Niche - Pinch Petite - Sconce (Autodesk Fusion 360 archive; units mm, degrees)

design "Elongated Sconce - Pinch Petite" references "Elongated Sconce - Helio", "Pinch Petite"
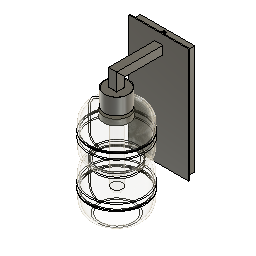
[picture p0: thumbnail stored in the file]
external_derived "ExternalDerived1" bodies "Back Plate", "Knurled Shade Ring", "Screw Top", "Socket Cover", "Screw Bottom", "Socket - E26", "Sconce", "T9-Bulb"
derived_instance "DerivedInstance1"
derived_instance "DerivedInstance2"
derived_instance "DerivedInstance3"
derived_instance "DerivedInstance4"
derived_instance "DerivedInstance5"
derived_instance "DerivedInstance6"
derived_instance "DerivedInstance7"
derived_instance "DerivedInstance8"
derived_instance "DerivedInstance9"
external_derived "ExternalDerived2" bodies "Body1"
align "Align1"
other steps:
derived_base_feature "Derived Base Feature1" bodies "Back Plate"
derived_base_feature "Derived Base Feature1" bodies "Knurled Shade Ring"
derived_base_feature "Derived Base Feature1" bodies "Screw Top"
derived_base_feature "Derived Base Feature1" bodies "Socket Cover"
derived_base_feature "Derived Base Feature1" bodies "Screw Bottom"
derived_base_feature "Derived Base Feature1" bodies "Socket - E26"
derived_base_feature "Derived Base Feature1" bodies "Sconce"
derived_base_feature "Derived Base Feature1" bodies "T9-Bulb"
derived_base_feature "Derived Base Feature1" bodies "E26 Base"
derived_base_feature "Derived Base Feature2" bodies "Body1"
derived_base_feature "Derived Base Feature" bodies "Back Plate", "Screw Top", "Knurled Shade Ring", "Body34"
create_component "CreateComponent1"
create_component "CreateComponent2"
create_component "CreateComponent3"
create_component "CreateComponent4"
create_component "CreateComponent5"
create_component "CreateComponent6"
create_component "CreateComponent7"
create_component "CreateComponent8"
create_component "CreateComponent9"
named bodies: "Back Plate", "Screw Top", "Knurled Shade Ring", "Body1", "Body34", "Sconce", "Socket Cover", "Screw Bottom", "Socket - E26", "T9-Bulb", "E26 Base"

design "Elongated Sconce - Helio"
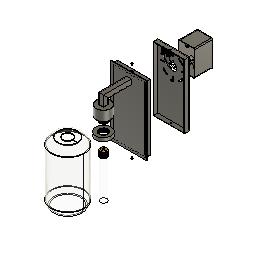
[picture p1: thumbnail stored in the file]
derived_base_feature "Derived Base Feature1" bodies "T9-Bulb", "Helio"
derived_base_feature "Derived Base Feature2" bodies "Back Plate", "Socket Cover", "Screw Top", "Screw Bottom", "Knurled Shade Ring", "Socket - E26"
derived_base_feature "Derived Base Feature3" bodies "E26 Base"
move "Move1"
component_from_bodies "Body->Comp1"
component_from_bodies "Body->Comp2"
component_from_bodies "Body->Comp3"
component_from_bodies "Body->Comp4"
component_from_bodies "Body->Comp5"
component_from_bodies "Body->Comp6"
component_from_bodies "Body->Comp7"
component_from_bodies "Body->Comp8"
component_from_bodies "Body->Comp9"
component_from_bodies "Body->Comp10"
derived_base_feature "Derived Base Feature5" bodies "screw1", "screw1 (1)", "Body1"
move "Move3"
move "Move4"
move "Move5"
move "Move6"
component_from_bodies "Body->Comp11"
component_from_bodies "Body->Comp12"
component_from_bodies "Body->Comp13"
component_from_bodies "Body->Comp14"
component_from_bodies "Body->Comp15"
component_from_bodies "Body->Comp16"
component_from_bodies "Body->Comp17"
component_from_bodies "Body->Comp18"
component_from_bodies "Body->Comp19"
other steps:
base_feature "Base Feature1" bodies "T9-Bulb"
base_feature "Base Feature1" bodies "E26 Base"
base_feature "Base Feature1" bodies "Body1"
base_feature "Base Feature1" bodies "Body1 (1) (1)"
base_feature "Base Feature1" bodies "Body9"
base_feature "Base Feature1" bodies "Body7"
base_feature "Base Feature1" bodies "Body6"
base_feature "Base Feature1" bodies "screw1"
base_feature "Base Feature1" bodies "Body4"
base_feature "Base Feature1" bodies "screw1 (1)"
base_feature "Base Feature1" bodies "Body1 (1)"
base_feature "Base Feature1" bodies "Helio"
base_feature "Base Feature1" bodies "Back Plate"
base_feature "Base Feature1" bodies "Knurled Shade Ring"
base_feature "Base Feature1" bodies "Screw Top"
base_feature "Base Feature1" bodies "Sconce"
base_feature "Base Feature1" bodies "Socket Cover"
base_feature "Base Feature1" bodies "Screw Bottom"
base_feature "Base Feature1" bodies "Socket - E26"
create_component "CreateComponent1"
remove_body "RemoveBody1"
create_component "CreateComponent2"
remove_body "RemoveBody2"
create_component "CreateComponent3"
remove_body "RemoveBody3"
create_component "CreateComponent4"
remove_body "RemoveBody4"
create_component "CreateComponent5"
remove_body "RemoveBody5"
create_component "CreateComponent6"
remove_body "RemoveBody6"
create_component "CreateComponent7"
remove_body "RemoveBody7"
create_component "CreateComponent8"
remove_body "RemoveBody8"
create_component "CreateComponent9"
remove_body "RemoveBody9"
create_component "CreateComponent10"
remove_body "RemoveBody10"
create_component "CreateComponent11"
remove_body "RemoveBody11"
create_component "CreateComponent12"
remove_body "RemoveBody12"
create_component "CreateComponent13"
remove_body "RemoveBody13"
create_component "CreateComponent14"
remove_body "RemoveBody14"
create_component "CreateComponent15"
remove_body "RemoveBody15"
create_component "CreateComponent16"
remove_body "RemoveBody16"
create_component "CreateComponent17"
remove_body "RemoveBody17"
create_component "CreateComponent18"
remove_body "RemoveBody18"
create_component "CreateComponent19"
remove_body "RemoveBody19"
named bodies: "T9-Bulb", "Helio", "Back Plate", "Socket Cover", "Screw Top", "Screw Bottom", "Knurled Shade Ring", "Socket - E26", "Body34", "Sconce", "E26 Base", "screw1", "screw1 (1)", "Body1", "Body1 (1)", "Body4", "Body6", "Body7", "Body1 (1) (1)", "Body9"

design "Pinch Petite"
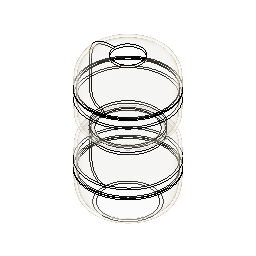
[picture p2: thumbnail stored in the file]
